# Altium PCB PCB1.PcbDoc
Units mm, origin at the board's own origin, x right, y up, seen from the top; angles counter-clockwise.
Board outline 99.24 x 66.22 mm, 2 copper layers (Top Layer, Bottom Layer); 114 components, 90 nets, 416 pads, 135 vias.
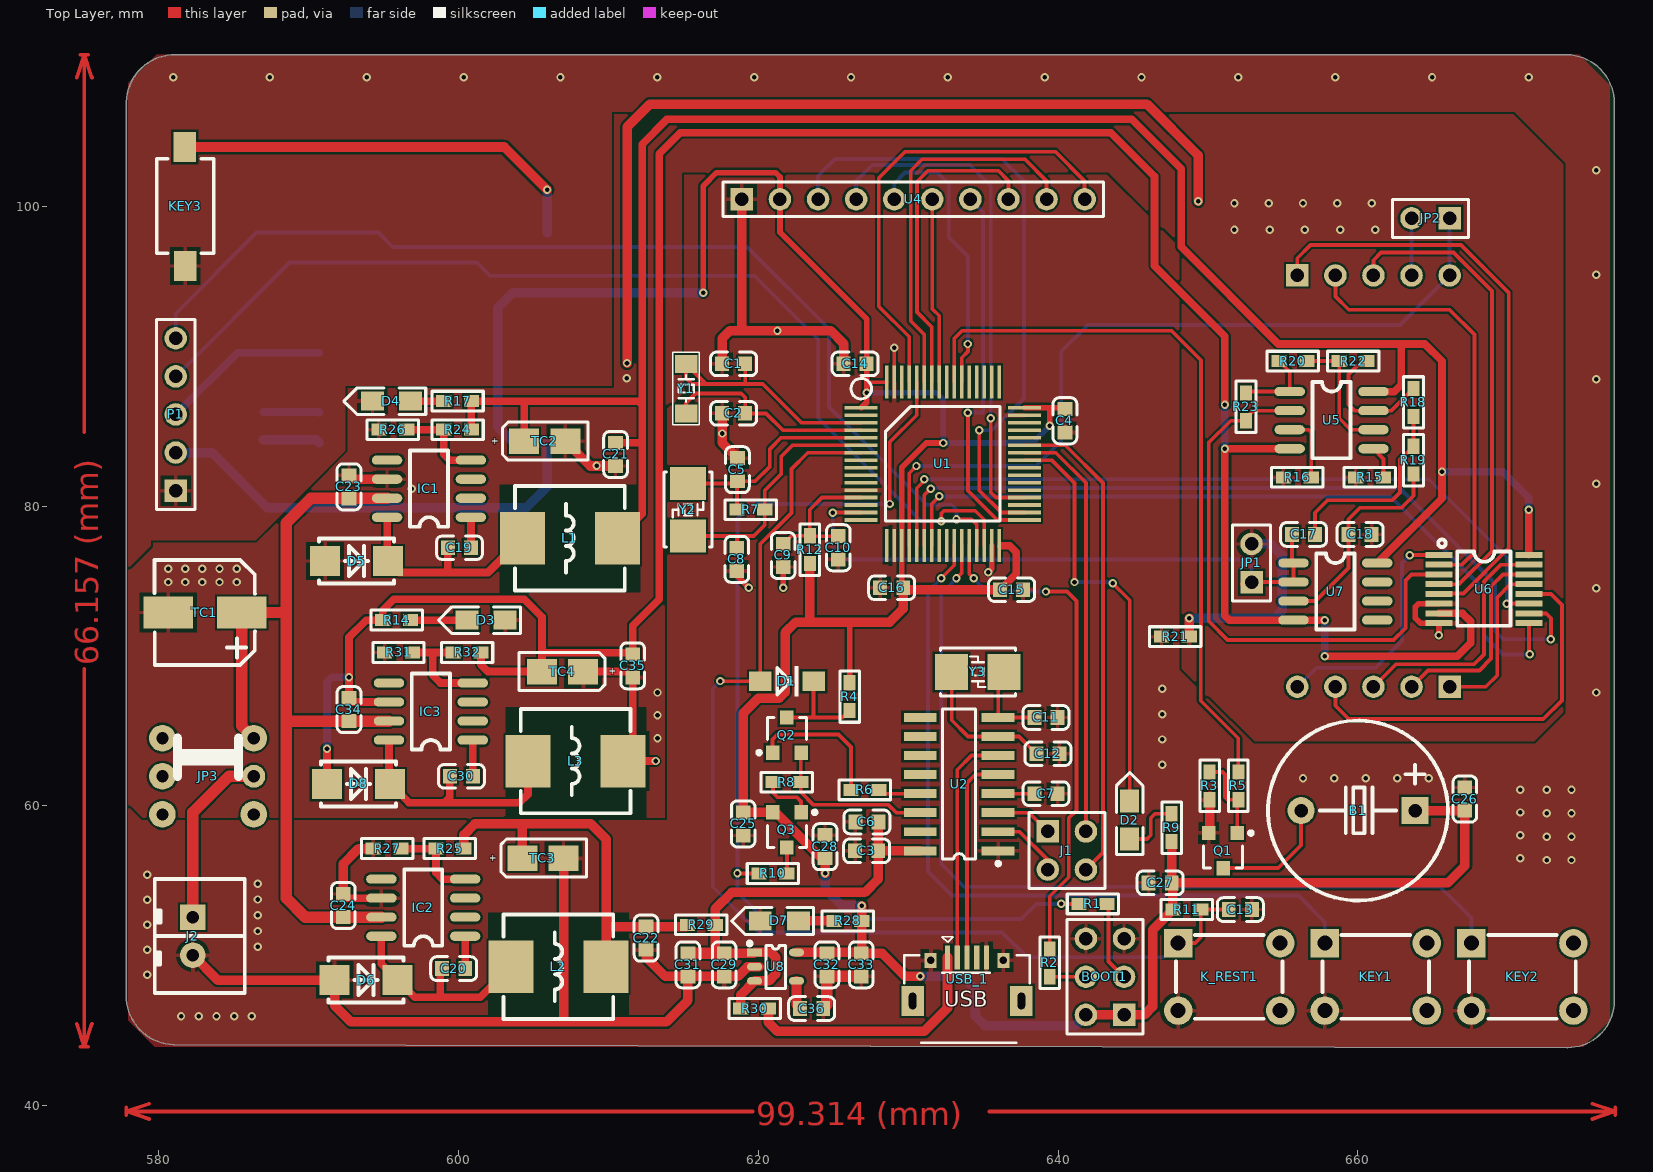
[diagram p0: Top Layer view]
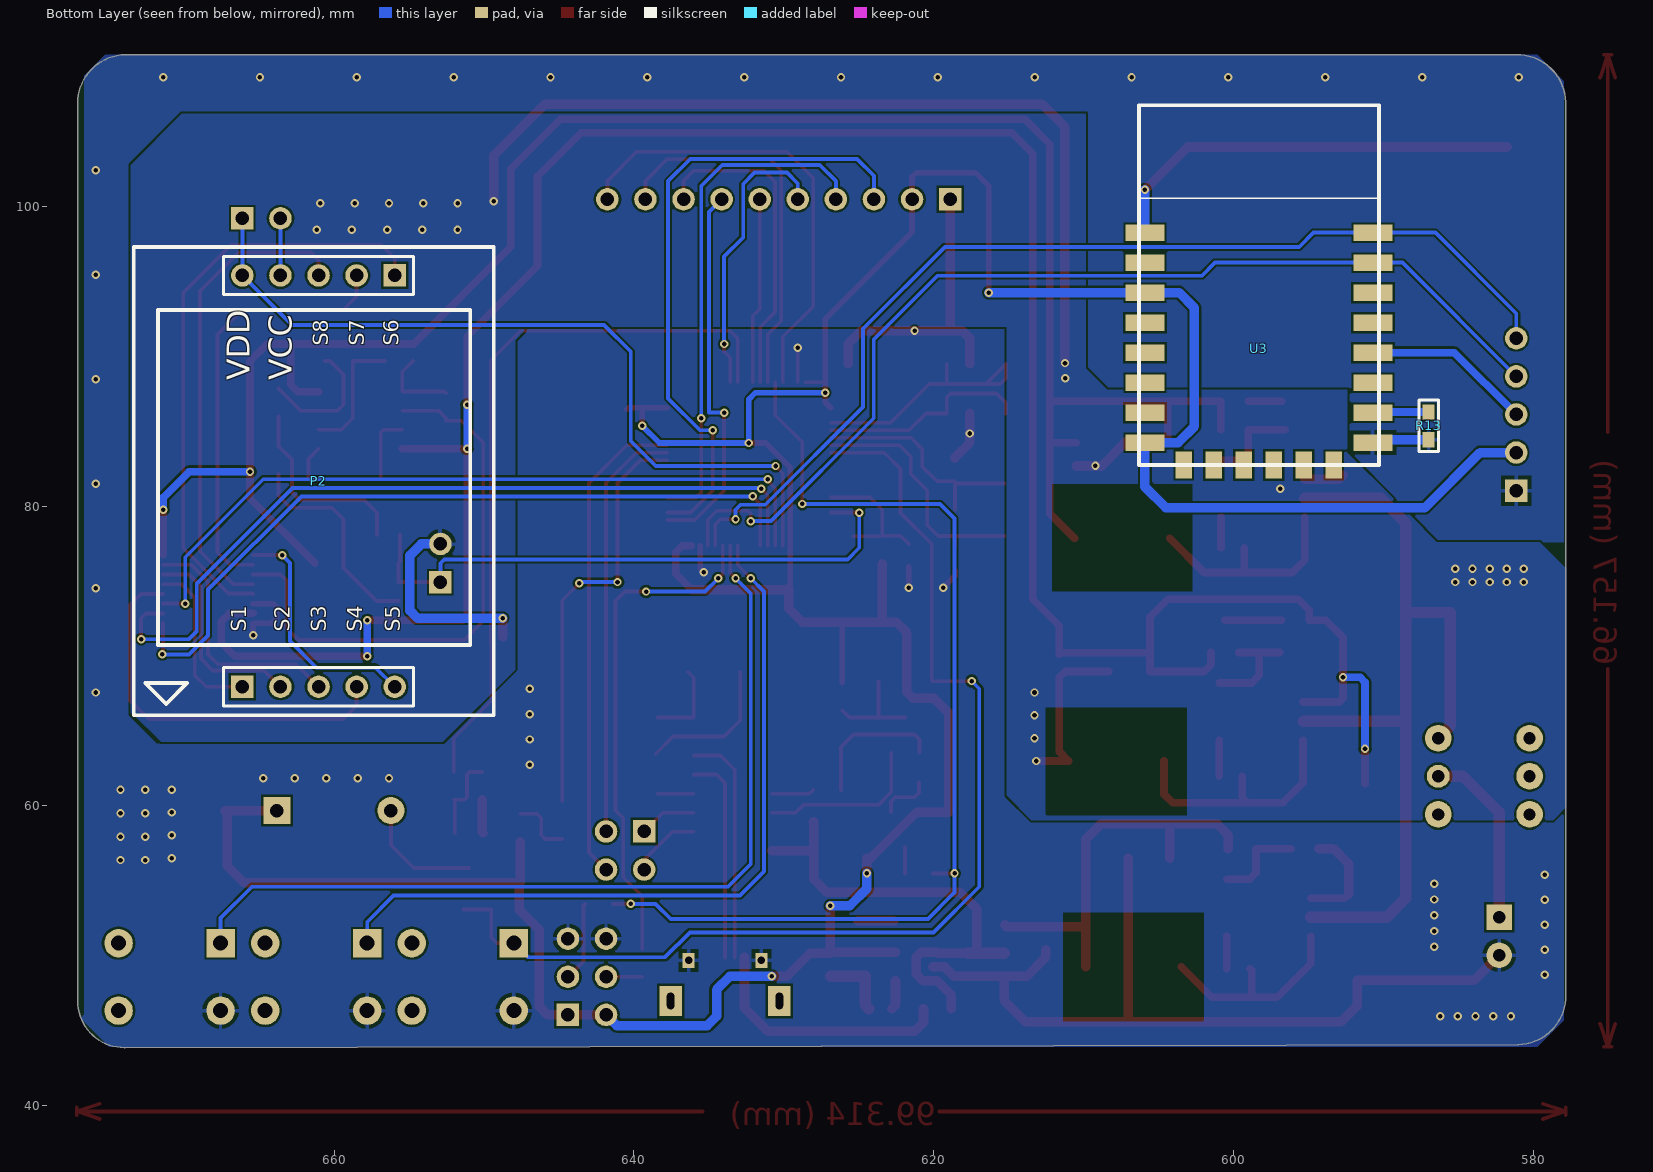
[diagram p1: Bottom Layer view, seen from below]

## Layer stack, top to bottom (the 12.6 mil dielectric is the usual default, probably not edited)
Top Solder: solder mask 0.0102, Solder Resist, Dk 3.5
Top Layer: signal copper 0.0356
Dielectric 1: dielectric 0.32, FR-4, Dk 4.8
Bottom Layer: signal copper 0.0356
Bottom Solder: solder mask 0.0102, Solder Resist, Dk 3.5

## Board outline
577.86,47.374 ccw(c581.089,47.307) 581.02,44.079 ccw(c581.024,44.269) 581.023,44.079 673.92,43.879 ccw(c673.92,44.069) 673.953,43.881 ccw(c673.989,44.069) 673.989,43.878 ccw(c673.989,46.99) 677.101,46.99 677.101,106.804 ccw(c673.872,106.872) 677.102,106.872 ccw(c673.872,106.872) 673.941,110.101 ccw(c673.937,109.91) 673.916,110.099 581.154,110.099 cw(c581.087,106.87) 581.156,110.099 581.154,110.099 ccw(c581.087,106.87) 577.858,106.939 ccw(c578.049,106.935) 577.86,106.914

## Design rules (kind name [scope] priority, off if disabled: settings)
Clearance [All] p1: gap=0.152 ignorepadtopadclearanceinfootprint=TRUE
HoleSize [All] p1: absolutevalues=TRUE maxlimit=3.81 minlimit=0.025 maxpercent=80.000 minpercent=20.000
PolygonConnect [All] p1: thpad.connectstyle=Relief thpad.reliefconductorwidth=0.254 thpad.reliefentries=4 thpad.polygonreliefangle="90 Angle" thpad.airgapwidth=0.254 smdpad.connectstyle=Relief smdpad.reliefconductorwidth=0.254 smdpad.reliefentries=4 smdpad.polygonreliefangle="90 Angle" smdpad.airgapwidth=0.254 via.connectstyle=Direct via.reliefconductorwidth=0.254 via.reliefentries=4 via.polygonreliefangle="90 Angle" via.airgapwidth=0.254
RoutingVias [All] p1: holewidth=0.305 width=0.559 viastyle="Through Hole" minholewidth=0.305 minwidth=0.559 maxholewidth=0.305 maxwidth=0.559
SilkToSilkClearance [All] p1: silktosilkclearance=0.102
SilkToSolderMaskClearance [IsPad] p1: minsilkscreentomaskgap=0.051 clearancetoexposedcopper=TRUE
SolderMaskExpansion [All] p1: expansion=0.064
Width PWR [InNetClass('PWR')] p1: maxlimit=1.524 minlimit=0.254 preferedwidth=0.508
Width [All] p2: maxlimit=1.27 minlimit=0.254 preferedwidth=0.254
27 further rules are at their usual default settings.

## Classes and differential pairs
net class PWR: AGND GND USB_VCC VCC3.3 VCC5V VDD VDD5V VEE

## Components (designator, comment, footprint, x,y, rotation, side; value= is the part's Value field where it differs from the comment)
B1 "DC5V" "BEEP 7.6x12x7.5" 663.809,59.69 r180 top
BOOT1 "VCC5" HDR2X3 644.398,46.063 r90 top
C1 "22" LC-0603_C 618.363,89.479 r0 top
C2 "22" LC-0603_C 618.363,86.178 r0 top
C3 "100nF" LC-0603_C 627.237,57.006 r0 top
C4 "100nF" LC-0603_C 640.461,85.687 r90 top
C5 "22" LC-0603_C 618.617,82.423 r270 top
C6 "10uF" LC-0603_C 627.253,58.928 r0 top
C7 "100nF" LC-0603_C 639.199,60.816 r0 top
C8 "22" LC-0603_C 618.579,76.446 r90 top
C9 "10uF" LC-0603_C 621.665,76.7 r270 top
C10 "100nF" LC-0603_C 625.348,77.216 r270 top
C11 "22" LC-0603_C 639.191,65.896 r180 top
C12 "22" LC-0603_C 639.318,63.483 r180 top
C13 "100nF" LC-0603_C 652.153,53.086 r180 top
C14 "100nF" LC-0603_C 626.467,89.479 r0 top
C15 "100nF" LC-0603_C 636.905,74.422 r180 top
C16 "100nF" LC-0603_C 628.904,74.549 r0 top
C17 "1uF" LC-0603_C 656.374,78.105 r180 top
C18 "0.33uF" LC-0603_C 660.146,78.105 r180 top
C19 "10nF" LC-0603_C 600.075,77.216 r0 top
C20 "10nF" LC-0603_C 599.694,49.149 r0 top
C21 "100nF" LC-0603_C 610.489,83.439 r270 top
C22 "100nF" LC-0603_C 612.521,51.181 r270 top
C23 "100nF" LC-0603_C 592.709,81.28 r270 top
C24 "100nF" LC-0603_C 592.328,53.348 r270 top
C25 "100nF" LC-0603_C 618.998,58.801 r270 top
C26 "100nF" LC-0603_C 667.131,60.452 r90 top
C27 "100nF" LC-0603_C 646.811,54.864 r180 top
C28 "100nF" LC-0603_C 624.459,57.277 r90 top
C29 "1uF" LC-0603_C 617.728,49.403 r270 top
C30 "10nF" LC-0603_C 600.202,61.976 r0 top
C31 "100nF" LC-0603_C 615.315,49.403 r270 top
C32 "100nF" LC-0603_C 624.586,49.403 r270 top
C33 "1uF" LC-0603_C 626.872,49.403 r270 top
C34 "100nF" LC-0603_C 592.709,66.421 r270 top
C35 "100nF" LC-0603_C 611.632,69.342 r90 top
C36 "22nF" LC-0603_C 623.57,46.482 r0 top
D1 "1N4148" DIODE_SOP 620.133,68.309 r0 top
D2 "LED" LED-0805B 644.779,57.785 r90 top
D3 "LED" LED-0805B 603.123,72.39 r180 top
D4 "LED" LED-0805B 596.811,86.995 r180 top
D5 "SS54" LC-SMA(DO-214AC)_S2 593.217,76.327 r180 top
D6 "SS54" LC-SMA(DO-214AC)_S2 593.852,48.387 r180 top
D7 "LED" LED-0805B 622.681,52.324 r180 top
D8 "SS34" LC-SMA(DO-214AC)_S2 593.344,61.468 r180 top
IC1 "TPS5430" SOP8 600.837,79.248 r180 top
IC2 "TPS5430" SOP8 600.456,51.308 r180 top
IC3 "TPS5430" SOP8 600.964,64.389 r180 top
J1 "Pin HDR2X2" "Pin HDR2X2/2.54mm-S" 639.318,58.293 r270 top
J2 "HDR-1X2" XH2.54-2P 582.295,52.578 r270 top
JP1 "HDR-1X2" HDR1X2 652.907,74.93 r90 top
JP2 "HDR-1X2" HDR1X2 666.115,99.187 r180 top
JP3 "POWER" 6脚开关 586.359,59.436 r180 top
K_REST1 "KEY_M" DIP-6X6X5 648.012,50.847 r0 top
KEY1 "KEY_M" DIP-6X6X5 657.791,50.847 r0 top
KEY2 "KEY_M" DIP-6X6X5 667.57,50.847 r0 top
KEY3 "KEY_M" SMD-3X6X2.5 581.787,103.886 r270 top
L1 "10uH" L-SMD-0630 607.441,77.851 r0 top
L2 "10uH" L-SMD-0630 606.679,49.276 r0 top
L3 "10uH" L-SMD-0630 607.822,62.992 r0 top
P1 "Header 5" HDR1X5 581.152,81.026 r90 top
P2 "senor" "sensor-con pin 10" 661.289,81.661 r90 bottom
Q1 "S8050" SOT-23R 651.002,57.15 r180 top
Q2 "S8050" SOT-23R 621.911,64.594 r0 top
Q3 "S8550" SOT-23R 621.911,58.53 r180 top
R1 "10K" "R 0603_M" 642.328,53.467 r0 top
R2 "10K" "R 0603_M" 639.445,49.53 r90 top
R3 "10K" "R 0603_M" 650.113,61.341 r90 top
R4 "10K" "R 0603_M" 626.102,67.293 r270 top
R5 "1K" "R 0603_M" 652.018,61.341 r90 top
R6 "1K" "R 0603_M" 627.118,61.07 r180 top
R7 "1M" "R 0603_M" 619.506,79.756 r180 top
R8 "1K" "R 0603_M" 621.911,61.578 r180 top
R9 "510" "R 0603_M" 647.581,58.547 r90 top
R10 "1K" "R 0603_M" 620.984,55.499 r180 top
R11 "10K" "R 0603_M" 648.589,53.086 r180 top
R12 "10R" "R 0603_M" 623.443,77.089 r270 top
R13 "1K" "R 0603_M" 586.994,85.344 r90 bottom
R14 "1K" "R 0603_M" 595.884,72.39 r180 top
R15 "500K" "R 0603_M" 660.781,81.915 r0 top
R16 "500K" "R 0603_M" 655.955,81.915 r0 top
R17 "1K" "R 0603_M" 599.948,86.995 r0 top
R18 "14.3K" "R 0603_M" 663.702,86.906 r270 top
R19 "53.6K" "R 0603_M" 663.702,83.058 r270 top
R20 "500K" "R 0603_M" 655.663,89.662 r0 top
R21 "0k" "R 0603_M" 647.827,71.288 r0 top
R22 "500K" "R 0603_M" 659.676,89.662 r0 top
R23 "500K" "R 0603_M" 652.526,86.614 r90 top
R24 "10K" "R 0603_M" 599.948,85.09 r0 top
R25 "10K" "R 0603_M" 599.44,57.15 r0 top
R26 "3.24K" "R 0603_M" 595.63,85.09 r0 top
R27 "3.24K" "R 0603_M" 595.249,57.15 r0 top
R28 "1K" "R 0603_M" 625.983,52.324 r0 top
R29 "0K" "R 0603_M" 616.204,52.07 r0 top
R30 "0K" "R 0603_M" 619.76,46.482 r180 top
R31 "10K" "R 0603_M" 596.011,70.231 r180 top
R32 "3.24K" "R 0603_M" 600.583,70.231 r180 top
TC1 "680UF" SMD-EC6.3X6.3X10 585.565,72.898 r180 top
TC2 "100uF" TAJ-A/3216 604.346,84.328 r0 top
TC3 "100uF" TAJ-A/3216 604.227,56.515 r0 top
TC4 "100uF" TAJ-A/3216 608.377,68.961 r180 top
U1 "STM32F103RCT6" LQFP64 626.872,86.558 r0 top
U2 "CH340G" SOP16M 633.408,61.451 r90 top
U3 "ESP8266-12" ESP8266-12 598.063,92.516 r180 bottom
U4 "SPI-LCD" Fe-HDR1X10/2.54-S 618.912,100.457 r90 top
U5 "LT1462" SOP8 655.447,87.63 r0 top
U6 "ADG658" ADG658-SOP-16 668.02,74.93 r0 top
U7 "LT1462" SOP8 655.701,76.2 r0 top
U8 "ME6211" SOT23-5 621.157,49.276 r0 top
USB_1 "USB1" USB-micro_B 632.626,49.89 r0 top
Y1 "32.768K" "OSC 3215-2P" 615.188,87.828 r90 top
Y2 "8M" "OSC 5032-2P" 615.315,79.756 r90 top
Y3 "12M" "OSC 5032-2P" 634.656,68.944 r0 top

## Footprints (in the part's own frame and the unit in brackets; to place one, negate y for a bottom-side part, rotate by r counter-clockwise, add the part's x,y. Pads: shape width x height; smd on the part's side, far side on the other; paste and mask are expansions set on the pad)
6脚开关 [mil]
  round 70 hole 32: 1(0,0) 3(0,-200) 4(240,-200) 5(240,-100) 6(240,0)
  round 60 hole 32: 2(0,-100)
  silkscreen extent 40,-200 200,-100, body extent -37,-257 277,57, height 118
ADG658-SOP-16 [mil]
  rect 71x16 smd: 1(-103.11,71.21) 2(-103.11,45.62) 3(-103.11,20.03) 4(-103.11,-5.56) 5(-103.11,-31.15) 6(-103.11,-56.74) 7(-103.11,-82.33) 8(-103.11,-107.92) 9(133.11,-107.92) 10(133.11,-82.33) 11(133.11,-56.74) 12(133.11,-31.15) 13(133.11,-5.56) 14(133.11,20.03) 15(133.11,45.62) 16(133.11,71.21)
  silkscreen extent -105,-115 85,112
"BEEP 7.6x12x7.5" [mm]
  rect 1.8x1.8 hole 0.9: 1(0,0)
  round 1.8 hole 0.9: 2(7.6,0)
  silkscreen extent -2.19,-6 9.81,6, body extent -2.19,-5.97 9.81,6.03, height 7.55
DIODE_SOP [mm]
  rect 1.5x1.3 smd: 1(0,0) 2(3.556,0)
  silkscreen extent 1.14,-1.02 2.56,1.02
DIP-6X6X5 [mm]
  rect 1.9x1.9 hole 1: 1(0,0)
  round 1.9 hole 1: 2(0,-4.5) 3(6.8,-4.5) 4(6.8,0)
  silkscreen extent -0.16,-5.04 6.96,0.54, body extent -0.8,-5.24 7.41,0.76, height 4.95
ESP8266-12 [mm]
  rect 2.6x1.1 smd: 1(-7.854,5.718) 2(-7.854,3.718) 3(-7.854,1.718) 4(-7.854,-0.282) 5(-7.854,-2.282) 6(-7.854,-4.282) 7(-7.854,-6.282) 8(-7.854,-8.282) 15(7.346,-8.282) 16(7.346,-6.282) 17(7.346,-4.282) 18(7.346,-2.282) 19(7.346,-0.282) 20(7.346,1.718) 21(7.346,3.718) 22(7.346,5.718)
  rect 1.1x1.8 smd: 9(-5.254,-9.782) 10(-3.254,-9.782) 11(-1.254,-9.782) 12(0.746,-9.782) 13(2.746,-9.782) 14(4.746,-9.782)
  silkscreen extent -8.25,-9.78 7.75,14.22
Fe-HDR1X10/2.54-S [mm]
  rect 1.5x1.5 hole 0.9: 1(0,0)
  round 1.5 hole 0.9: 2(0,-2.54) 3(0,-5.08) 4(0,-7.62) 5(0,-10.16) 6(0,-12.7) 7(0,-15.24) 8(0,-17.78) 9(0,-20.32) 10(0,-22.86)
  silkscreen extent -1.14,-24.13 1.14,1.27, body extent -1.25,-24.26 1.25,1.4, height 3.2
HDR1X2 [mm] "Connector; Header; 2 Position"
  rect 1.5x1.5 hole 0.9: 1(0,0)
  round 1.5 hole 0.9: 2(2.54,0)
  silkscreen extent -1.27,-1.27 3.81,1.27, body extent -1.27,-1.02 3.81,1.52, height 8.34
HDR1X5 [mm] "Connector; Header; 5 Position"
  rect 1.5x1.5 hole 0.9: 1(0,0)
  round 1.5 hole 0.9: 2(2.54,0) 3(5.08,0) 4(7.62,0) 5(10.16,0)
  silkscreen extent -1.27,-1.27 11.43,1.27
HDR2X3 [mm]
  rect 1.5x1.5 hole 0.9: 1(0,0)
  round 1.5 hole 0.9: 2(0,2.54) 3(2.54,0) 4(2.54,2.54) 5(5.08,0) 6(5.08,2.54)
  silkscreen extent -1.27,-1.27 6.35,3.81
L-SMD-0630 [mm]
  rect 3x3.5 smd: 1(-3.175,0) 2(3.175,0)
  silkscreen extent -3.66,-3.48 3.66,3.48, body extent -3.47,-3.3 3.47,3.3, height 3.05
LC-0603_C [mm]
  rect 0.93x0.98 smd: 1(-0.77,0) 2(0.77,0)
  silkscreen extent -1.54,-0.79 1.54,0.79, body extent -0.8,-0.4 0.8,0.4, height 0.3
LC-SMA(DO-214AC)_S2 [mm]
  rect 2x2 smd: 1(2.1,0) 2(-2.1,0)
  silkscreen extent -2.5,-1.5 2.5,1.5
LED-0805B [mil]
  rect 60x50 smd: A(0,0) K(100,0)
  silkscreen extent -40,-35 175,35, body extent 10,-25 89,25, height 32
LQFP64 [mm]
  rect 2.2x0.254 smd: 1(0,0) 2(0,-0.5) 3(0,-1) 4(0,-1.5) 5(0,-2) 6(0,-2.5) 7(0,-3) 8(0,-3.5) 9(0,-4) 10(0,-4.5) 11(0,-5) 12(0,-5.5) 13(0,-6) 14(0,-6.5) 15(0,-7) 16(0,-7.5) 33(10.9,-7.5) 34(10.9,-7) 35(10.9,-6.5) 36(10.9,-6) 37(10.9,-5.5) 38(10.9,-5) 39(10.9,-4.5) 40(10.9,-4) 41(10.9,-3.5) 42(10.9,-3) 43(10.9,-2.5) 44(10.9,-2) 45(10.9,-1.5) 46(10.9,-1) 47(10.9,-0.5) 48(10.9,0)
  rect 0.254x2.2 smd: 17(1.7,-9.2) 18(2.2,-9.2) 19(2.7,-9.2) 20(3.2,-9.2) 21(3.7,-9.2) 22(4.2,-9.2) 23(4.7,-9.2) 24(5.2,-9.2) 25(5.7,-9.2) 26(6.2,-9.2) 27(6.7,-9.2) 28(7.2,-9.2) 29(7.7,-9.2) 30(8.2,-9.2) 31(8.7,-9.2) 32(9.2,-9.2) 49(9.2,1.7) 50(8.7,1.7) 51(8.2,1.7) 52(7.7,1.7) 53(7.2,1.7) 54(6.7,1.7) 55(6.2,1.7) 56(5.7,1.7) 57(5.2,1.7) 58(4.7,1.7) 59(4.2,1.7) 60(3.7,1.7) 61(3.2,1.7) 62(2.7,1.7) 63(2.2,1.7) 64(1.7,1.7)
  silkscreen extent -0.68,-7.56 9.26,1.95
"OSC 3215-2P" [mm]
  rect 1.2x1.5 smd: 1(-1.65,0) 2(1.65,0)
  silkscreen extent -2.41,-0.89 2.41,0.89, body extent -1.47,-0.76 1.73,0.74, height 0.61
"OSC 5032-2P" [mm]
  rect 2.2x2.4 smd: 1(-1.75,0) 2(1.75,0)
  silkscreen extent -2.5,-1.6 2.5,1.6, body extent -2.5,-1.52 2.5,1.68, height 0.86
"Pin HDR2X2/2.54mm-S" [mm] "Connector; Header; 2x2 Position"
  rect 1.5x1.5 hole 0.9: 1(0,0)
  round 1.5 hole 0.9: 2(0,2.54) 3(2.54,0) 4(2.54,2.54)
  silkscreen extent -1.27,-1.27 3.81,3.81, body extent -1.27,-1.27 3.81,3.81, height 7.58
"R 0603_M" [mil]
  rect 40x31.5 smd: 1(-36.5,0) 2(36.5,0)
  silkscreen extent -68,-26 68,26, body extent -31,-16 31,16, height 16
"sensor-con pin 10" [mm]
  rect 1.5x1.5 hole 0.9: 1(-13.716,4.826) 6(13.716,-5.334)
  round 1.5 hole 0.9: 2(-13.716,2.286) 3(-13.716,-0.254) 4(-13.716,-2.794) 5(-13.716,-5.334) 7(13.716,-2.794) 8(13.716,-0.254) 9(13.716,2.286) 10(13.716,4.826)
  silkscreen extent -15.62,-11.94 15.62,12.07
SMD-3X6X2.5 [mm]
  rect 2x1.5 smd: 1(-0.059,-0.02) 2(7.874,0)
  silkscreen extent 0.73,-1.9 7.03,1.9, body extent -0.19,-1.78 7.81,1.72, height 2.59
SMD-EC6.3X6.3X10 [mm]
  rect 3.3x2.132 smd: 1(0.021,0) 2(4.921,0)
  silkscreen extent -0.88,-3.5 5.84,3.5, body extent -1.09,-3.3 5.91,3.3, height 5.4
SOP8 [mil]
  oval 80x24 smd: 1(0,0) 2(0,-50) 3(0,-100) 4(0,-150) 5(220,-150) 6(220,-100) 7(220,-50) 8(220,0)
  silkscreen extent 60,-175 160,25, body extent -9,-174 229,24, height 63
SOP16M [mm]
  rect 0.6x2.2 smd: 1(-4.445,-2.6) 2(-3.175,-2.6) 3(-1.905,-2.6) 4(-0.635,-2.6) 5(0.635,-2.6) 6(1.905,-2.6) 7(3.175,-2.6) 8(4.445,-2.6) 9(4.445,2.6) 10(3.175,2.6) 11(1.905,2.6) 12(0.635,2.6) 13(-0.635,2.6) 14(-1.905,2.6) 15(-3.175,2.6) 16(-4.445,2.6)
  silkscreen extent -5.42,-2.72 5,1.1
SOT23-5 [mil]
  rect 40x20 smd: 1(-55,37.4)
  oval 40x20 smd: 2(-55,0) 3(-55,-37.4) 4(55,-37.4) 5(55,37.4)
  silkscreen extent -73,-57 26,66, body extent -55,-57 55,57, height 43
SOT-23R [mm]
  rect 0.9x0.95 smd: 1(0.95,-1.048) 2(-0.95,-1.048) 3(0,1.302)
  silkscreen extent -1.98,-1.17 1.3,1.3
TAJ-A/3216 [mm]
  rect 2x1.7 smd: 1(0.047,0) 2(2.794,0)
  silkscreen extent -1.4,-1.27 4.32,1.27, body extent -0.2,-0.8 3,0.8, height 1.6
USB-micro_B [mm]
  rect 1.5x2 hole 0.5 slot 1.1 at 90 deg: 0(-2.325,-2.9) 0(4.925,-2.9)
  rect 0.35x1.6 smd: 1(0,0) 2(0.65,0) 3(1.3,0) 4(1.95,0) 5(2.6,0)
  rect 0.8x1 hole 0.5: 5(-1.125,-0.19) 5(3.725,-0.19)
  silkscreen extent -2.89,-5.69 5.49,1.4, body extent -2.7,-5.6 5.3,0, height 2.8
XH2.54-2P [mm]
  rect 1.7x1.7 hole 0.83: 1(0,0)
  round 1.7 hole 0.83: 2(2.54,0)
  silkscreen extent -2.54,-2.54 5.06,3.46, body extent -2.45,-2.37 4.95,3.38, height 7

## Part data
B1: library part BEEP, "蜂鸣器"
BOOT1: library part "Header 3X2", "Header, 3-Pin, Dual row"
C1 C2 C4 C5 C8 C9 C10 C14 C15 C16: library part C_1, "无极性贴片电容"
C3 C6 C7 C11 C12 C13 C19 C20 C21 C22 C23 C24 C25 C26 C27 C28 C29 C30 C31 C32 C33 C34 C35 C36: library part C
C17 C18: library part C, "无极性贴片电容"
D1: library part D
D5 D6: "肖特基二极管"
D8: library part SS54, "肖特基二极管"
J2: library part "Header 2_1", "2P接插件"
JP1 JP2: library part "Header 2", "2P接插件"
JP3: library part 6角开关
L1 L2 L3: library part L-CDRH, "功率屏蔽电感"
P1: "Header, 5-Pin"
Q1 Q2: library part NPN, "8050/BCW846/BCW847"
Q3: library part PNP, "8550/BCW68"
R1 R2 R3 R4 R5 R6 R7 R8 R9 R10 R11 R12 R13 R14 R15 R16 R17 R18 R19 R20 R21 R22 R23 R24 R25 R26 R27 R28 R29 R30 R31 R32: library part R, "贴片电阻"
TC1 TC2 TC3 TC4: library part TCAP_1, "钽电容"
U1: library part STM32F103RDT6
U2: "USB2UART"
U5 U7: library part LT1462_1
USB_1: library part USB5
Y1 Y2 Y3: library part XTAL_2, "Crystal Oscillator"

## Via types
v1: diameter 0.559, hole 0.305, Top Layer to Bottom Layer, tented both sides, 135 vias

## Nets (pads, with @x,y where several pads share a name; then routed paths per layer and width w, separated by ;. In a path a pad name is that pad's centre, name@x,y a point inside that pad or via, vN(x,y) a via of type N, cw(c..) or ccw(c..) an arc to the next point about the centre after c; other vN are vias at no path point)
A0: U1.21 U6.11 | length 50.2
  Top Layer w0.254: U1.21 630.572,81.186 631.072,81.686 v1(631.072,81.788) ; v1(669.925,73.489) U6.11
  Bottom Layer w0.254: v1(631.072,81.788) 664.718,81.788 669.925,76.581 v1(669.925,73.489)
A1: U1.22 U6.10 | length 54.4
  Top Layer w0.254: U1.22 631.072,80.724 v1(631.501,81.153) ; U6.10 672.553,72.839 672.875,72.517 672.875,71.135 v1(672.86,71.12)
  Bottom Layer w0.254: v1(631.501,81.153) 631.552,81.204 662.762,81.204 669.163,74.803 669.163,71.628 669.671,71.12 v1(672.86,71.12)
A2: U1.23 U6.9 | length 51.1
  Top Layer w0.254: U1.23 631.572,80.138 v1(632.079,80.645) ; U6.9 671.401,70.152 v1(671.449,70.104)
  Bottom Layer w0.254: v1(632.079,80.645) 662.178,80.645 668.401,74.422 668.401,71.374 669.671,70.104 v1(671.449,70.104)
ADC1: C17.2 JP1.1 U1.15 U7.1 U7.2 | length 40.1
  Top Layer w0.254: v1(624.967,79.558) U1.15 ; JP1.1@652.272,74.803 JP1.1@652.399,74.93 ; JP1.1 U7.2 U7.1 655.604,76.297 C17.2
  Bottom Layer w0.254: v1(624.967,79.558) 624.967,77.216 625.742,76.441 652.653,76.441 652.907,76.187 JP1.1
AGND: C18.1 C21.2 C23.1 C35.1 D3.A D4.K D5.1 IC1.6 JP1.2 L3.2 R15.1 R16.1 R21.2 R26.1 R31.2 TC1.2 TC2.2 TC4.1 U6.6 U6.8 | length 95.7
  Top Layer w0.381: v1(665.401,71.374) U6.8 664.157,72.189 663.829,72.517 663.829,73.279 664.039,73.489 U6.6
  Top Layer w0.508: TC4.1 611.243,68.961 C35.1 611.632,63.627 L3.2 v1(613.156,62.992)
  Top Layer w0.635: C23.1 592.971,81.788 IC1.6 ; TC2.2 608.799,82.669 C21.2 ; v1(611.251,89.535) 611.251,105.283 612.775,106.807 645.922,106.807 649.351,103.378 v1(649.351,100.33) ; R21.2 v1(648.754,72.517)
  Bottom Layer w0.635: v1(648.754,72.517) 654.431,72.517 654.939,73.025 654.939,76.708 654.177,77.47 JP1.2
  other v1: 613.283,64.516 613.283,66.04 613.283,67.564 580.644,74.93 581.787,74.93 582.93,74.93 584.073,74.93 585.216,74.93 580.644,75.819 581.787,75.819 582.93,75.819 584.073,75.819 585.216,75.819 596.9,81.153 609.219,82.677 611.243,88.519 651.764,98.425 654.113,98.425 656.463,98.425 658.812,98.425 661.162,98.425 651.764,100.203 654.05,100.203 656.336,100.203 658.622,100.203 660.908,100.203
BEEP: R5.2 U1.55 | length 48.9
  Top Layer w0.254: U1.55 633.072,91.163 633.603,91.694 647.573,91.694 649.541,89.725 649.541,70.773 649.516,70.747 649.516,67.018 652.018,64.516 R5.2
BOOT0: R1.1 R10.2 U1.60 | length 69.7
  Top Layer w0.254: v1(618.617,55.499) R10.2 ; v1(628.777,80.137) 628.777,84.263 630.572,86.058 U1.60 ; v1(640.207,53.467) R1.1
  Bottom Layer w0.254: v1(628.777,80.137) 619.595,80.137 618.617,79.159 v1(618.617,55.499) 618.617,54.229 618.833,54.013 620.395,52.451 637.54,52.451 638.556,53.467 v1(640.207,53.467)
BOOT1: R2.2 U1.28 | length 33.7
  Top Layer w0.254: U1.28 634.072,75.477 v1(634.365,75.184) ; v1(639.191,74.295) 640.588,74.295 641.223,73.66 641.223,59.69 640.715,59.182 640.715,55.245 639.445,53.975 R2.2
  Bottom Layer w0.254: v1(634.365,75.184) 635.254,74.295 v1(639.191,74.295)
"CH340 D+": U2.5 USB_1.3 | length 14
  Top Layer w0.254: USB_1.3 633.926,61.537 634.475,62.086 U2.5
"CH340 D-": U2.6 USB_1.2 | length 15.6
  Top Layer w0.254: USB_1.2 633.276,62.411 634.221,63.356 U2.6
DAC1: JP2.1 P2.10 U1.20 | length 53.6
  Top Layer w0.254: U1.20 630.072,82.186 v1(630.555,82.669)
  Bottom Layer w0.254: v1(630.555,82.669) 638.548,82.669 640.207,84.328 640.207,90.297 641.985,92.075 662.813,92.075 P2.10 JP2.1
G: JP2.2 P2.9 | length 3.8
  Bottom Layer w0.254: P2.9 JP2.2
GND: BOOT1.5 BOOT1.6 C1.1 C2.1 C3.1 C4.1 C5.1 C6.1 C7.2 C8.1 C9.2 C10.2 C11.1 C12.1 C13.1 C14.1 C15.1 C16.1 C22.2 C24.1 C25.2 C26.2 C27.2 C28.2 C29.2 C31.2 C32.2 C33.2 C36.2 D6.1 D7.K IC2.6 J2.2 K_REST1.2 KEY1.2 KEY2.2 KEY3.2 P1.1 Q1.1 R3.1 R13.1 R21.1 R27.1 TC3.2 U1.12 U1.18 U1.31 U1.47 U1.63 U2.1 U3.15 U4.1 U8.2 USB_1.5 | length 106.5
  Top Layer w0.254: U1.63 v1(629.072,90.551)
  Top Layer w0.381: C8.1 618.579,75.349 v1(619.379,74.549) ; v1(621.665,74.549) C9.2 ; v1(635.344,75.591) 635.572,75.819 U1.31
  Top Layer w0.508: C24.1 592.598,53.848 IC2.6
  Top Layer w0.635: J2.2 583.946,48.387 D6.1 591.752,46.677 592.836,45.593 606.894,45.593 ; C24.1 592.328,56.134 593.344,57.15 R27.1 ; TC3.2 607.021,45.72 606.894,45.593 ; C22.2 612.521,49.911 613.799,48.633 C31.2 ; C2.1 617.593,84.217 C5.1 ; C1.1 617.593,91.178 618.109,91.694 619.133,91.694 ; U4.1 618.912,91.915 619.133,91.694 ; U8.2@620.086,49.259 619.278,49.259 618.652,48.633 C29.2 C31.2 ; C14.1 625.697,90.837 624.84,91.694 619.133,91.694 ; Q1.1 650.113,58.259 R3.1 ; 606.894,45.593 613.88,45.593 615.315,47.028 C31.2
  Top Layer w0.762: C36.2 624.586,46.728 C32.2 C33.2
  Bottom Layer w0.635: R13.1 590.534,84.417 U3.15
  other v1: 581.508,45.974 582.689,45.974 583.87,45.974 585.051,45.974 586.232,45.974 579.247,48.73 579.247,50.4 586.613,50.6 586.613,51.652 579.247,52.07 586.613,52.705 579.247,53.74 586.613,53.758 586.613,54.81 579.247,55.41 672.592,56.388 674.243,56.388 670.814,56.515 672.592,57.954 674.243,57.954 670.814,58.039 672.592,59.521 674.243,59.521 670.814,59.563 670.814,61.087 672.592,61.087 674.243,61.087 656.336,61.849 658.431,61.849 660.527,61.849 662.622,61.849 664.718,61.849 646.938,62.738 646.938,64.431 646.938,66.125 675.894,67.564 646.938,67.818 675.894,74.528 675.894,81.492 617.601,84.836 675.894,88.455 621.284,91.694 675.894,95.419 675.894,102.383 580.977,108.585 587.436,108.585 593.895,108.585 600.354,108.585 606.812,108.585 613.271,108.585 619.73,108.585 626.189,108.585 632.648,108.585 639.107,108.585 645.566,108.585 652.024,108.585 658.483,108.585 664.942,108.585 671.401,108.585
GPIO0: P1.3 U3.18 | length 11.3
  Bottom Layer w0.508: P1.3 585.28,90.234 U3.18
KEY1: KEY1.1 U1.26 | length 51.7
  Top Layer w0.254: v1(632.206,75.184) 633.072,76.051 U1.26
  Bottom Layer w0.254: v1(632.206,75.184) 631.317,74.295 631.317,55.635 632.926,54.026 656.031,54.026 657.791,52.266 KEY1.1
KEY2: KEY2.1 U1.27 | length 60.3
  Top Layer w0.254: v1(633.222,75.185) 633.572,75.535 U1.27
  Bottom Layer w0.254: v1(633.222,75.185) 632.206,74.169 632.206,56.134 633.73,54.61 665.48,54.61 667.57,52.52 KEY2.1
LED1: D2.K U1.41 | length 28.1
  Top Layer w0.254: U1.41 639.572,83.058 641.096,81.534 v1(641.096,74.93) ; v1(643.636,74.854) 644.779,73.711 D2.K
  Bottom Layer w0.254: v1(641.096,74.93) 643.56,74.93 v1(643.636,74.854)
NetB1_2: B1.2 Q1.3 | length 8.2
  Top Layer w0.254: Q1.3 654.683,55.848 656.209,57.374 B1.2
NetBOOT1_3: BOOT1.3 R1.2 | length 5.3
  Top Layer w0.254: R1.2 643.369,53.353 643.369,49.632 BOOT1.3
NetBOOT1_4: BOOT1.4 R2.1 | length 2.4
  Top Layer w0.254: R2.1 BOOT1.4
NetC7_1: C7.1 U2.4 | length 2.4
  Top Layer w0.254: U2.4 C7.1
NetC9_1: C9.1 C10.1 R12.1 U1.13 | length 9.4
  Top Layer w0.254: C9.1 622.211,78.016 R12.1 ; C10.1 623.473,77.986 R12.1 ; U1.13 624.245,80.558 623.443,79.756 R12.1
NetC11_2: C11.2 U2.8 Y3.2 | length 5.6
  Top Layer w0.254: Y3.2 636.008,68.546 U2.8 C11.2
NetC12_2: C12.2 U2.7 Y3.1 | length 9.8
  Top Layer w0.254: Y3.1 632.906,65.713 633.993,64.626 U2.7 637.405,64.626 C12.2
NetC17_1: C17.1 R18.2 R19.1 | length 13.1
  Top Layer w0.254: C17.1 657.144,79.548 657.987,80.391 662.305,80.391 662.813,80.899 662.813,83.096 R19.1 R18.2
NetC18_2: C18.2 R19.2 U7.3 | length 14.3
  Top Layer w0.254: U7.3 657.174,73.66 659.376,75.862 C18.2 659.376,79.113 660.146,79.883 662.9,79.883 663.702,80.685 R19.2
NetC19_1: C19.1 D5.2 IC1.8 L1.1 | length 14.8
  Top Layer w0.508: IC1.8 595.249,76.395 D5.2 596.079,75.565 599.313,75.565 ; C19.1 599.305,75.573 599.313,75.565 ; L1.1 601.98,75.565 599.313,75.565
NetC19_2: C19.2 IC1.1 | length 2
  Top Layer w0.508: IC1.1 600.845,79.24 C19.2
NetC20_1: C20.1 D6.2 IC2.8 L2.1 | length 14.2
  Top Layer w0.508: IC2.8 594.868,49.471 D6.2 597.095,47.244 598.805,47.244 ; C20.1 598.805,49.03 598.805,47.244 ; L2.1 601.472,47.244 598.805,47.244
NetC20_2: C20.2 IC2.1 | length 2.2
  Top Layer w0.508: IC2.1 600.464,51.3 C20.2
NetC23_2: C23.2 C24.2 C34.2 IC1.7 IC2.7 IC3.7 JP3.3 TC1.1 | length 57.7
  Top Layer w0.762: JP3.3 585.544,65.331 TC1.1 588.391,72.898 ; IC2.7 C24.2 589.788,52.578 588.518,53.848 588.518,65.659 ; IC1.7 592.717,80.518 C23.2 590.161,80.51 588.518,78.867 588.518,65.659 ; IC3.7 595.368,65.651 C34.2 592.701,65.659 588.518,65.659
NetC30_1: C30.1 D8.2 IC3.8 L3.1 | length 17.1
  Top Layer w0.508: IC3.8 595.376,61.536 D8.2 596.714,60.198 599.059,60.198 ; C30.1 599.432,60.571 599.059,60.198 ; L3.1 604.647,60.787 604.058,60.198 599.059,60.198
NetC30_2: C30.2 IC3.1 | length 2.4
  Top Layer w0.508: IC3.1 600.972,64.381 C30.2
NetC36_1: C36.1 U8.4 | length 1.9
  Top Layer w0.635: U8.4 622.554,46.728 C36.1
NetD1_2: D1.2 Q2.3 R4.2 | length 6.8
  Top Layer w0.254: Q2.3 623.697,65.896 ; D1.2 623.689,65.904 623.697,65.896 ; R4.2 625.632,65.896 623.697,65.896
NetD2_A: D2.A R9.2 | length 4.2
  Top Layer w0.254: D2.A 645.922,57.785 646.176,58.039 646.176,59.182 646.468,59.474 R9.2
NetD3_K: D3.K R14.1 | length 3.8
  Top Layer w0.508: R14.1 D3.K
NetD4_A: D4.A R17.1 | length 2.2
  Top Layer w0.508: D4.A R17.1
NetD7_A: D7.A R28.1 | length 2.4
  Top Layer w0.635: D7.A R28.1
NetIC1_4: IC1.4 R24.1 R26.2 | length 6.1
  Top Layer w0.508: R26.2 R24.1 599.021,83.469 599.432,83.058 IC1.4
NetIC2_4: IC2.4 R25.1 R27.2 | length 6.1
  Top Layer w0.508: R27.2 R25.1 598.513,55.537 598.932,55.118 IC2.4
NetIC3_4: IC3.4 R31.1 R32.2 | length 7.1
  Top Layer w0.508: R31.1 598.297,70.231 ; R32.2 598.297,70.231 ; IC3.4 598.805,68.199 598.297,68.707 598.297,70.231
NetJ2_1: J2.1 JP3.2 | length 12
  Top Layer w0.762: J2.1 582.295,59.563 584.708,61.976 JP3.2
NetQ1_2: Q1.2 R3.2 R5.1 | length 5.8
  Top Layer w0.254: R3.2 650.964,62.268 651.129,62.103 651.129,60.579 651.294,60.414 R5.1@651.886,60.414 ; Q1.2 651.952,60.348 R5.1@651.886,60.414 ; R5.1 R5.1@651.886,60.414
NetQ2_1: Q2.1 R8.1 U2.14 | length 11.2
  Top Layer w0.254: Q2.1 622.838,63.523 R8.1 622.838,60.93 623.697,60.071 628.691,60.071 629.216,59.546 U2.14
NetQ2_2: Q2.2 R6.2 | length 9.5
  Top Layer w0.254: Q2.2 620.961,64.439 621.292,64.77 625.348,64.77 626.191,63.927 R6.2
NetQ3_2: Q3.2 R8.2 | length 3.5
  Top Layer w0.254: R8.2 620.984,60.879 621.284,60.579 622.584,60.579 622.861,60.302 Q3.2
NetQ3_3: Q3.3 R10.1 | length 1.7
  Top Layer w0.254: R10.1 Q3.3
NetR6_1: R6.1 U2.13 | length 2.9
  Top Layer w0.254: R6.1 628.299,60.816 U2.13
NetR13_2: R13.2 U3.16 | length 3.7
  Bottom Layer w0.508: R13.2 590.68,86.271 U3.16
NetR15_2: R15.2 U5.5 | length 2.2
  Top Layer w0.254: U5.5 661.708,83.147 R15.2
NetR16_2: R16.2 U5.3 | length 4.5
  Top Layer w0.254: U5.3 656.693,85.09 656.882,84.901 R16.2
NetR18_1: R18.1 R22.2 U5.7 | length 8.7
  Top Layer w0.254: R22.2 660.273,89.662 659.376,88.765 659.376,86.749 659.765,86.36 U5.7 662.229,86.36 R18.1
NetR20_1: R20.1 R23.2 U5.1 | length 5.3
  Top Layer w0.254: R23.2 652.615,87.63 U5.1 655.447,88.951 R20.1
NetR20_2: R20.2 R22.1 U5.6 | length 8.6
  Top Layer w0.254: R20.2 R22.1 658.749,85.852 659.511,85.09 U5.6
NetR23_1: R23.1 U5.2 U6.3 | length 37.8
  Top Layer w0.254: U5.2 653.034,86.36 652.526,85.852 R23.1 651.512,85.687 650.052,84.227 650.052,72.324 651.307,71.069 662.381,71.069 663.194,71.882 663.194,75.057 663.576,75.439 U6.3
PA9: J1.2 U1.42 | length 28.2
  Top Layer w0.254: U1.42 639.85,83.558 641.858,81.55 J1.2
PA10: J1.4 U1.43 | length 32.5
  Top Layer w0.254: U1.43 640.477,84.058 643.001,81.534 643.001,56.896 J1.4
PB5: U1.57 U4.6 | length 12.4
  Top Layer w0.254: U4.6 631.612,93.149 632.072,92.689 U1.57
PB6: U1.58 U4.8 | length 21.7
  Top Layer w0.254: U1.58 631.572,91.947 630.583,92.936 630.583,101.628 631.317,102.362 636.016,102.362 636.692,101.686 U4.8
PB7: U1.59 U4.9 | length 25.7
  Top Layer w0.254: U1.59 631.072,91.431 630.174,92.329 630.174,102.362 630.936,103.124 637.794,103.124 639.232,101.686 U4.9
PB8: U1.61 U4.10 | length 31
  Top Layer w0.254: U1.61 630.072,91.288 628.043,93.317 628.043,101.882 629.793,103.632 639.826,103.632 641.772,101.686 U4.10
PB12: U1.33 U4.7 | length 25.4
  Top Layer w0.254: v1(633.984,86.233) 633.984,81.018 635.944,79.058 U1.33
  Bottom Layer w0.254: v1(633.984,86.233) 635,86.233 635,99.609 U4.7
PB13: U1.34 U4.3 | length 42.4
  Top Layer w0.254: v1(634.746,85.058) 634.746,81.031 636.219,79.558 U1.34
  Bottom Layer w0.254: U4.3 623.992,102.022 625.119,103.149 636.245,103.149 637.721,101.673 637.721,87.176 635.603,85.058 v1(634.746,85.058)
PB15: U1.36 U4.4 | length 34.1
  Top Layer w0.254: v1(635.508,85.852) 635.508,80.899 635.849,80.558 U1.36
  Bottom Layer w0.254: U4.4 626.532,101.666 627.609,102.743 634.111,102.743 635.508,101.346 v1(635.508,85.852)
PC14: C1.2 U1.3 Y1.2 | length 17.1
  Top Layer w0.254: C1.2 619.133,88.146 619.125,88.138 ; U1.3 622.886,85.558 620.306,88.138 619.125,88.138 ; 616.528,88.138 619.125,88.138 ; 616.528,88.138 615.569,88.138 615.188,88.519 Y1.2 616.528,88.138
PC15: C2.2 U1.4 Y1.1 | length 14.3
  Top Layer w0.254: Y1.1 615.188,86.868 615.823,87.503 618.871,87.503 619.133,87.241 C2.2 620.529,86.178 621.649,85.058 U1.4
PD0: C5.2 R7.2 U1.5 Y2.2 | length 15.4
  Top Layer w0.254: Y2.2 618.47,81.506 C5.2@618.579,81.615 ; R7.2 C5.2@618.579,81.615 ; U1.5 621.53,84.558 620.776,83.804 620.776,82.639 619.79,81.653 C5.2 C5.2@618.579,81.615
PD1: C8.2 R7.1 U1.6 Y2.1 | length 16.9
  Top Layer w0.254: Y2.1 618.617,78.006 ; C8.2 618.579,77.968 618.617,78.006 ; U1.6 622.284,84.058 621.538,83.312 621.538,82.141 620.433,81.036 R7.1 620.433,78.74 619.699,78.006 618.617,78.006
PD2: U1.54 U4.5 | length 19.2
  Top Layer w0.254: U1.54 633.572,89.885 633.984,90.297 v1(633.984,90.805)
  Bottom Layer w0.254: U4.5 629.072,101.514 629.793,102.235 631.952,102.235 632.714,101.473 632.714,97.917 633.984,96.647 v1(633.984,90.805)
RESET: C13.2 D1.1 K_REST1.1 R11.1 U1.7 | length 75.5
  Top Layer w0.254: v1(617.474,68.326) 617.491,68.309 D1.1 620.133,77.462 622.211,79.54 622.211,82.469 623.3,83.558 U1.7 ; K_REST1.1 649.144,50.847 649.516,51.219 R11.1 C13.2
  Bottom Layer w0.254: v1(617.474,68.326) 616.966,67.818 616.966,54.61 620.014,51.562 636.27,51.562 637.921,49.911 647.076,49.911 K_REST1.1
RXD: J1.1 U2.3 | length 3.8
  Top Layer w0.254: U2.3 638.065,59.546 J1.1
S1: P2.1 U6.13 | length 11.2
  Top Layer w0.254: P2.1 668.528,67.945 669.29,68.707 669.29,73.9 670.179,74.789 U6.13
S2: P2.2 U6.14 | length 13.8
  Top Layer w0.254: P2.2 664.667,69.037 668.096,69.037 668.884,69.825 668.884,74.651 669.672,75.439 U6.14
S3: P2.3 U6.15 | length 16.6
  Top Layer w0.254: P2.3 662.534,69.444 667.741,69.444 668.401,70.104 668.401,74.955 669.534,76.089 U6.15
S4: P2.4 U6.12 | length 26.1
  Top Layer w0.254: P2.4 658.495,66.675 659.384,65.786 672.355,65.786 673.608,67.039 673.608,73.406 672.875,74.139 U6.12
S5: P2.5 U6.1 | length 16.1
  Top Layer w0.254: v1(663.448,76.708) 663.479,76.739 U6.1
  Bottom Layer w0.254: P2.5 657.225,69.215 661.162,69.215 662.94,70.993 662.94,76.2 v1(663.448,76.708)
S6: P2.6 U6.5 | length 39.9
  Top Layer w0.254: P2.6 655.955,96.52 656.844,97.409 666.877,97.409 670.052,94.234 670.052,77.181 667.039,74.168 665.43,74.168 U6.5
S7: P2.7 U6.2 | length 29
  Top Layer w0.254: P2.7 658.495,93.98 659.384,93.091 666.115,93.091 667.766,91.44 667.766,76.904 666.951,76.089 U6.2
S8: P2.8 U6.4 | length 32
  Top Layer w0.254: P2.8 661.035,96.393 661.543,96.901 666.369,96.901 668.932,94.338 668.932,76.985 666.736,74.789 U6.4
TXD: J1.3 U2.2 | length 4.7
  Top Layer w0.254: U2.2 637.43,58.276 639.318,56.388 J1.3
USART3_RX: P1.5 U1.29 U3.22 | length 70.2
  Top Layer w0.254: v1(633.222,79.121) 634.216,79.121 634.572,78.765 U1.29
  Bottom Layer w0.254: P1.5 581.152,92.837 586.549,98.234 U3.22 594.678,98.234 595.63,97.282 619.252,97.282 624.713,91.821 624.713,86.614 631.241,80.086 632.892,80.086 633.222,79.756 v1(633.222,79.121)
USART3_TX: P1.4 U1.30 U3.21 | length 69.8
  Top Layer w0.254: v1(632.206,78.994) 632.206,79.502 632.384,79.68 634.472,79.68 635.072,79.08 U1.30
  Bottom Layer w0.254: P1.4 588.74,96.234 U3.21 601.25,96.234 602.122,95.362 619.76,95.362 624.007,91.115 624.007,85.852 630.865,78.994 v1(632.206,78.994)
USB_VCC: R30.1 USB_1.1 | length 17.1
  Top Layer w0.635: R30.1 620.687,45.555 621.284,44.958 631.063,44.958 632.626,46.521 USB_1.1
VCC3.3: B1.1 BOOT1.1 BOOT1.2 C4.2 C14.2 C15.2 C16.2 C25.1 C26.1 C27.1 C28.1 C32.1 C33.1 P1.2 Q3.1 R4.1 R9.1 R11.2 R12.2 R28.2 U1.1 U1.19 U1.32 U1.48 U1.64 U3.3 U3.8 U4.2 U8.5 | length 242.7
  Top Layer w0.254: 627.294,88.258 U1.64 ; U1.32@636.072,77.295 U1.32
  Top Layer w0.381: v1(616.331,94.234) 616.331,101.346 617.22,102.235 621.157,102.235 621.452,101.94 U4.2 621.452,98.257 627.237,92.472 C14.2 627.237,88.201 ; R4.1 626.102,72.001 626.364,72.263 ; U1.1 627.237,86.923 v1(627.237,87.562) 627.237,88.201 ; 627.294,88.258 627.237,88.201 ; C16.2 629.572,74.651 U1.19 629.572,82.566 631.207,84.201 v1(632.333,84.201) ; U1.48 639.445,86.558 ; v1(639.445,85.344) 639.445,86.558 ; C4.2 640.36,86.558 639.445,86.558
  Top Layer w0.508: C15.2 637.207,75.494 637.207,76.929 636.778,77.358 U1.32@636.169,77.358
  Top Layer w0.635: U8.5 626.819,50.226 C33.1 ; R12.2 623.443,72.39 623.57,72.263 ; v1(624.459,55.499) C28.1 624.221,56.507 621.151,59.578 Q3.1 620.954,59.571 C25.1 618.998,66.167 620.02,67.189 621.401,67.189 621.792,67.58 621.792,71.554 622.501,72.263 623.57,72.263 ; v1(626.91,53.34) R28.2 626.91,50.211 C33.1 ; v1(630.808,48.633) 630.8,48.641 629.793,48.641 628.261,50.173 C33.1 ; C15.2 629.801,74.422 C16.2 629.674,73.16 628.777,72.263 626.364,72.263 623.57,72.263 ; BOOT1.2 BOOT1.1 645.757,46.063 646.303,46.609 646.303,51.727 R11.2 647.662,54.783 C27.1 ; R9.1 C27.1 ; B1.1 663.817,59.682 C26.1 667.305,59.682 667.131,59.508 667.131,56.007 665.988,54.864 C27.1
  Bottom Layer w0.381: v1(627.237,87.562) 631.893,87.562 632.333,87.122 v1(632.333,84.201) 638.302,84.201 v1(639.445,85.344)
  Bottom Layer w0.635: P1.2 583.565,83.566 587.248,79.883 604.52,79.883 605.917,81.28 U3.8 603.693,84.234 602.615,85.312 602.615,93.218 603.631,94.234 U3.3 v1(616.331,94.234) ; v1(624.459,55.499) 624.459,54.483 625.602,53.34 v1(626.91,53.34) ; v1(630.808,48.633) 633.611,48.633 634.492,47.752 634.492,45.974 635.127,45.339 641.134,45.339 BOOT1.2
VCC5V: C3.2 C6.2 C29.1 C31.1 R29.2 R30.2 U2.16 U8.1 U8.3 | length 32.2
  Top Layer w0.635: 617.093,50.173 617.131,50.211 R29.2 617.131,53.124 618.236,54.229 627.118,54.229 628.007,55.118 C3.2 ; C29.1 619.707,50.173 U8.1 620.842,50.226 621.157,49.911 621.157,48.768 620.715,48.326 U8.3 618.833,47.399 R30.2 ; C6.2 628.007,58.912 C3.2 ; U2.16 C3.2
  Top Layer w0.762: C31.1 617.093,50.173 C29.1
VDD: C21.1 L1.2 R17.2 R24.2 TC2.1 U5.8 U6.16 U7.8 | length 139
  Top Layer w0.508: R24.2 R17.2 604.266,86.995 ; TC2.1 604.393,86.868 604.266,86.995 ; C21.1 612.267,84.209 ; L1.2 612.267,79.502 612.267,84.209 ; U5.8 662.432,87.63 662.896,88.094 662.896,88.51 662.9,88.514 662.9,90.805 ; U7.8 665.607,80.518 v1(665.607,82.296) 665.607,89.662 664.464,90.805 662.9,90.805 ; U6.16 v1(671.401,79.756) ; 604.266,86.995 612.013,86.995 612.267,86.741 ; 612.267,84.209 612.267,86.741 ; 612.267,86.741 612.267,104.14 613.918,105.791 644.906,105.791 648.208,102.489 648.208,97.282 654.685,90.805 662.9,90.805
  Bottom Layer w0.508: v1(665.607,82.296) 669.671,82.296 671.401,80.566 v1(671.401,79.756)
VDD5V: C22.1 L2.2 R25.2 R29.1 TC3.1 | length 27.4
  Top Layer w0.635: R25.2 600.367,58.069 601.099,58.801 604.266,58.801 ; TC3.1 604.274,58.793 604.266,58.801 ; L2.2 609.854,51.943 ; R29.1 615.158,51.951 C22.1 609.862,51.951 609.854,51.943 ; 604.266,58.801 608.838,58.801 609.854,57.785 609.854,51.943
VEE: C34.1 C35.2 D8.1 IC3.6 R14.2 R32.1 TC4.2 U5.4 U6.7 U7.4 | length 172.3
  Top Layer w0.508: D8.1 v1(591.244,63.813) ; IC3.6 592.971,66.929 C34.1 v1(592.709,68.58) 592.709,71.247 593.852,72.39 R14.2 594.957,73.046 595.698,73.787 604.393,73.787 605.583,72.597 605.583,70.217 ; R32.1 601.51,69.431 601.98,68.961 TC4.2 605.583,70.217 ; C35.2 C35.2@611.632,70.217 ; v1(651.129,86.749) 651.129,91.313 646.43,96.012 646.43,101.981 643.509,104.902 614.807,104.902 613.41,103.505 613.41,73.787 611.632,72.009 C35.2@611.632,70.217 ; U5.4 v1(651.129,83.82) 651.129,72.697 651.436,72.39 U7.4 v1(657.791,72.39) ; v1(657.791,69.977) 666.623,69.977 667.512,70.866 667.512,72.298 666.971,72.839 U6.7 ; 605.583,70.217 C35.2@611.632,70.217
  Bottom Layer w0.508: v1(591.244,63.813) 591.244,68.258 591.566,68.58 v1(592.709,68.58) ; v1(651.129,83.82) v1(651.129,86.749) ; v1(657.791,69.977) v1(657.791,72.39)
WIFI_RESET: KEY3.1 U3.1 | length 28.2
  Top Layer w0.635: KEY3.1 603.064,103.945 v1(605.917,101.092)
  Bottom Layer w0.635: U3.1 v1(605.917,101.092)
pads on no net: IC1.2 IC1.3 IC1.5 IC2.2 IC2.3 IC2.5 IC3.2 IC3.3 IC3.5 JP3.1 JP3.4 JP3.5 JP3.6 K_REST1.3 K_REST1.4 KEY1.3 KEY1.4 KEY2.3 KEY2.4 U1.2 U1.8 U1.9 U1.10 U1.11 U1.14 U1.16 U1.17 U1.24 U1.25 U1.35 U1.37 U1.38 U1.39 U1.40 U1.44 U1.45 U1.46 U1.49 U1.50 U1.51 U1.52 U1.53 U1.56 U1.62 U2.9 U2.10 U2.11 U2.12 U2.15 U3.2 U3.4 U3.5 U3.6 U3.7 U3.9 U3.10 U3.11 U3.12 U3.13 U3.14 U3.17 U3.19 U3.20 U7.5 U7.6 U7.7 USB_1.0 USB_1.4
copper on no net: | length 148.8
  Top Layer w0.254: 574.548,45.466 575.056,43.942 ; 574.548,108.575 575.056,110.099 ; 574.802,43.942 575.31,43.942 ; 574.802,110.099 575.31,110.099 ; 575.056,69.124 575.056,43.942 ; 575.056,84.918 575.056,110.099 ; 575.564,45.466 575.056,43.942 ; 575.564,108.575 575.056,110.099 ; 577.85,39.37 577.85,39.878 ; 579.374,39.116 577.85,39.624 ; 579.374,40.132 577.85,39.624 ; 619.61,39.624 577.85,39.624 ; 635.404,39.624 677.164,39.624 ; 675.64,39.116 677.164,39.624 ; 675.64,40.132 677.164,39.624 ; 677.164,39.37 677.164,39.878

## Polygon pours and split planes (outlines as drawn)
GND on Top Layer "Top Layer-GND" (solid, pour order 10): 577.977,75.819 579.501,77.343 579.501,77.724 586.486,77.724 592.455,83.693 592.455,88.011 610.235,88.011 610.235,106.299 670.433,106.299 673.862,102.87 673.862,66.167 671.83,64.135 653.034,64.135 648.081,69.088 648.081,97.282 643.255,102.108 615.061,102.108 615.061,87.63 613.918,86.487 613.918,59.055 578.881,59.055 577.977,59.959 577.977,45.72 579.755,43.942 675.005,43.942 676.783,45.72 676.783,108.077 674.761,110.099 579.872,110.099 577.977,108.204
AGND on Top Layer "Top Layer-AGND" (solid, pour order 12): 577.977,75.819 577.977,59.959 578.881,59.055 614.49,59.055 614.49,87.058 615.061,87.63 615.061,102.108 643.255,102.108 648.081,97.282 648.081,69.088 653.034,64.135 671.83,64.135 673.862,66.167 673.862,102.87 670.37,106.362 670.306,106.299 609.854,106.299 609.854,88.011 592.455,88.011 592.455,83.693 586.486,77.724 579.501,77.724
no net on Top Layer "Top Layer-No Net" (solid, pour order 4): 639.969,105.918
no net on Top Layer "Top Layer-No Net 1" (solid, pour order 0): 570.611,70.612
GND on Bottom Layer "Bottom Layer-GND" (solid, pour order 16): 577.977,77.597 586.613,77.597 592.582,83.566 592.582,87.757 608.584,87.757 609.854,89.027 609.854,106.172 670.306,106.172 673.735,102.743 673.735,66.04 671.83,64.135 653.034,64.135 647.954,69.215 647.954,91.186 647.192,91.948 615.315,91.948 615.315,60.706 613.664,59.055 578.866,59.055 577.977,59.944 577.977,45.703 579.738,43.942 675.005,43.942 676.91,45.847 676.656,46.101 676.656,108.712 675.267,110.101 579.747,110.101 577.977,108.331
AGND on Bottom Layer "Bottom Layer-AGND" (solid, pour order 14): 577.812,75.819 579.59,77.597 586.448,77.597 592.544,83.693 592.417,83.82 592.417,87.757 608.419,87.757 609.854,89.192 609.854,106.172 670.141,106.172 673.57,102.743 673.57,66.167 673.443,66.167 671.538,64.262 652.742,64.262 647.916,69.088 647.916,91.059 647.027,91.948 615.15,91.948 615.15,60.706 613.499,59.055 578.701,59.055 577.812,59.944

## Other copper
Top Layer:
  pour cut-out: 601.975,52.908 601.975,45.725 601.98,45.72 611.402,45.72 611.402,52.908
  pour cut-out: 603.122,66.599 603.122,59.347 603.124,59.344 612.56,59.344 612.56,66.548 612.509,66.599
  pour cut-out: 602.742,81.458 612.182,81.458 612.182,74.201 602.767,74.201 602.742,74.226
  pour cut-out: 602.614,80.145
  text "66.157 (mm)" at 575.97,69.378 h1.52 r90
  text "99.314 (mm)" at 619.864,38.71 h1.52
Bottom Layer:
  pour cut-out: 608.965,80.01
  pour cut-out: 602.742,81.478 602.742,74.295 612.14,74.295 612.14,81.477
  pour cut-out: 603.123,66.548 603.123,59.38 612.465,59.38 612.521,59.436 612.521,66.548
  pour cut-out: 601.98,45.703 602.048,45.635 611.378,45.635 611.378,52.861 601.98,52.861

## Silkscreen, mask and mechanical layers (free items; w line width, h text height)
Mechanical 1:
  lines w0.381: 578.049,106.935 cw(c581.087,106.87) 581.152,109.909 673.937,109.909 ; 578.05,106.934 578.05,47.372 ccw(c581.089,47.307) 581.024,44.269 673.92,44.069 ; 673.937,109.91 cw(c673.872,106.872) 676.91,106.807 676.91,46.99 cw(c673.989,46.99) 673.989,44.069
